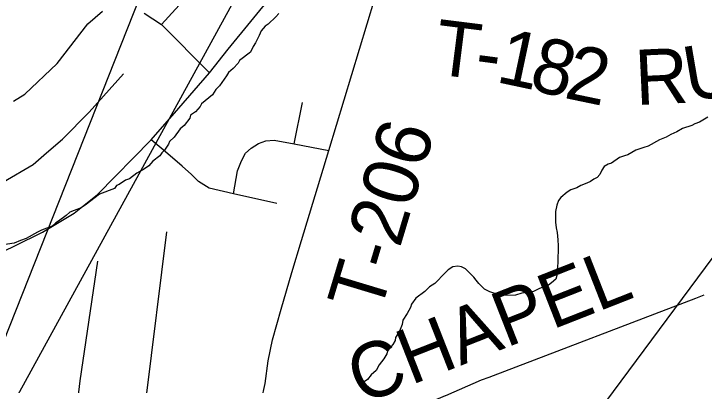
# Model space of a CAD drawing. Extents: x 0 to 39.3, y -3.9 to 22.
# Drawn here: x 4.426 to 5.137, y 18.792 to 19.174 of the extents above; entities that cross this region are included whole.
import ezdxf

# ---------------------------------------------------------------- set-up
doc = ezdxf.new("R2010")
doc.units = 0
for name, color, linetype in [('GM_X_County_Road', 7, 'Continuous'), ('GM_X_County_Road_Text', 7, 'Continuous'), ('GM_X_Minor_River', 7, 'Continuous'), ('GM_X_Township_Road', 7, 'Continuous'), ('GM_X_Township_Road_Text', 7, 'Continuous'), ('SH_Text', 7, 'Continuous')]:
    doc.layers.add(name, color=color, linetype=linetype)

msp = doc.modelspace()

# ---------------------------------------------------------------- linework, layer by layer
at = {"layer": 'GM_X_County_Road'}
msp.add_lwpolyline([(4.59461, 18.67238), (4.59645, 18.67311), (4.60116, 18.67478), (4.62281, 18.68243), (4.66904, 18.70101), (4.73306, 18.72672), (4.73764, 18.72856), (4.73983, 18.72947), (4.85676, 18.77589), (4.87046, 18.7815), (4.87082, 18.78165), (4.90761, 18.79768), (4.9155, 18.80062), (4.91988, 18.80226), (5.12824, 18.88192), (5.13704, 18.8851)], dxfattribs=at)
at = {"layer": 'GM_X_Minor_River'}
for points in [[(4.69882, 19.17461), (4.69572, 19.17124), (4.68762, 19.16378), (4.68454, 19.16155), (4.68066, 19.15706), (4.6783, 19.15215), (4.67475, 19.14461), (4.6724, 19.14085), (4.66964, 19.13481), (4.65809, 19.12627), (4.65691, 19.12362), (4.65149, 19.11801), (4.64686, 19.11391), (4.6449, 19.11052), (4.63751, 19.10038), (4.63364, 19.09665), (4.6305, 19.091), (4.61894, 19.08169), (4.61776, 19.07905), (4.61272, 19.07343), (4.60772, 19.0701), (4.60691, 19.06707), (4.60108, 19.05957), (4.59722, 19.05621), (4.591, 19.04757), (4.58598, 19.0431), (4.58517, 19.04045), (4.58088, 19.03406), (4.57818, 19.03144), (4.57623, 19.02843), (4.56891, 19.02286), (4.56465, 19.01799), (4.55926, 19.01428), (4.55235, 19.0106), (4.54503, 19.00464), (4.54083, 19.00319), (4.53429, 18.99874), (4.53161, 18.99765), (4.52928, 18.99465), (4.51397, 18.98883), (4.50049, 18.97842), (4.4951, 18.97471), (4.48325, 18.97035), (4.47977, 18.96699), (4.47168, 18.96105), (4.46899, 18.95919), (4.46513, 18.95584), (4.45404, 18.95185), (4.4502, 18.94963), (4.43831, 18.94337), (4.43257, 18.94119), (4.42606, 18.93826), (4.41005, 18.93588)], [(5.14069, 19.06795), (5.13224, 19.06278), (5.12727, 19.06134), (5.1242, 19.0595), (5.11464, 19.05624), (5.10888, 19.05292), (5.10238, 19.05037), (5.09776, 19.04741), (5.09088, 19.04487), (5.07936, 19.03823), (5.07478, 19.03679), (5.06637, 19.03427), (5.0583, 19.02947), (5.05487, 19.02839), (5.04951, 19.02658), (5.04143, 19.02064), (5.03799, 19.01956), (5.03377, 19.01735), (5.03143, 19.01359), (5.02945, 19.00906), (5.02674, 19.00606), (5.02328, 19.00422), (5.01983, 19.002), (5.01599, 19.00017), (5.00987, 18.99761), (5.00565, 18.9954), (4.99953, 18.99323), (4.99569, 18.99101), (4.98913, 18.98542), (4.9868, 18.98242), (4.9852, 18.9775), (4.98357, 18.97107), (4.98383, 18.96384), (4.98376, 18.96004), (4.98443, 18.95432), (4.98548, 18.94936), (4.98612, 18.94174), (4.9864, 18.93565), (4.98611, 18.91854), (4.98566, 18.91436), (4.98518, 18.90866), (4.98512, 18.90524), (4.98392, 18.90146), (4.97967, 18.89773), (4.97659, 18.89512), (4.96741, 18.89186), (4.96089, 18.88855), (4.95632, 18.88787), (4.94908, 18.88686), (4.94258, 18.88507), (4.92965, 18.88454), (4.92019, 18.88698), (4.91602, 18.8882), (4.91075, 18.89096), (4.90476, 18.89676), (4.90216, 18.90023), (4.89955, 18.90332), (4.89507, 18.90797), (4.89095, 18.91184), (4.88681, 18.9142), (4.88301, 18.91464), (4.87806, 18.91397), (4.87307, 18.91101), (4.86998, 18.90803), (4.85952, 18.8968), (4.85376, 18.89348), (4.84912, 18.88861), (4.83988, 18.88193), (4.83521, 18.87555), (4.8344, 18.87214), (4.83087, 18.86611), (4.82658, 18.85934), (4.82574, 18.85479), (4.82297, 18.848), (4.81905, 18.84122), (4.81862, 18.83818), (4.81627, 18.83404), (4.81084, 18.82805), (4.81003, 18.82464), (4.8069, 18.81937), (4.80223, 18.81337), (4.79909, 18.80734)], [(4.79909, 18.80734), (4.79369, 18.80287), (4.79019, 18.79798), (4.78558, 18.79502), (4.78172, 18.79205)]]:
    msp.add_lwpolyline(points, dxfattribs=at)
at = {"layer": 'GM_X_Township_Road'}
for p, q in [((4.57793, 19.16339), (4.63728, 19.22911)), ((4.71445, 19.04078), (4.72293, 19.08309))]:
    msp.add_line(p, q, dxfattribs=at)
for points in [[(4.67078, 18.71138), (4.67568, 18.74792), (4.68074, 18.77682), (4.68454, 18.79392), (4.68786, 18.8172), (4.69214, 18.83905), (4.70116, 18.8704), (4.71209, 18.9084), (4.72213, 18.94124), (4.75019, 19.0339), (4.80551, 19.21654)], [(4.26682, 18.90946), (4.29132, 18.90511), (4.33638, 18.90828), (4.37867, 18.91776), (4.40792, 18.92685), (4.4261, 18.93516), (4.45535, 18.94978), (4.48776, 18.96915), (4.51187, 18.98851), (4.56728, 19.04469), (4.59566, 19.07744), (4.62726, 19.11382), (4.64665, 19.13792), (4.69316, 19.19524)], [(4.42551, 19.08436), (4.43697, 19.09187), (4.47022, 19.12314), (4.50178, 19.16396), (4.51712, 19.17729)], [(4.55998, 19.17497), (4.57793, 19.16339), (4.62726, 19.11382)], [(4.25229, 18.98841), (4.26326, 18.98061), (4.2767, 18.97389), (4.29389, 18.97053), (4.31286, 18.96993), (4.32334, 18.97092), (4.34527, 18.97507), (4.36351, 18.97945), (4.36633, 18.98051), (4.36693, 18.98079), (4.38457, 18.98891), (4.41503, 19.00156), (4.44547, 19.01934), (4.4593, 19.0312), (4.4759, 19.04542), (4.50317, 19.07309), (4.53875, 19.11262)], [(4.69649, 18.97931), (4.65184, 18.98919), (4.62708, 18.99491), (4.61606, 19.00193), (4.60861, 19.00894), (4.59903, 19.01752), (4.5797, 19.03441), (4.56728, 19.04469)], [(4.65184, 18.98919), (4.65613, 19.0128), (4.66014, 19.02325), (4.66443, 19.03098), (4.67016, 19.03628), (4.67774, 19.04114), (4.68533, 19.04365), (4.69377, 19.04436), (4.71445, 19.04078), (4.75019, 19.0339)], [(4.41719, 18.76255), (4.47444, 18.7594), (4.49303, 18.75654), (4.53312, 18.75511), (4.54629, 18.75511), (4.55687, 18.7594), (4.56088, 18.7677), (4.56232, 18.78116), (4.58321, 18.95004)], [(4.53125, 18.64487), (4.52152, 18.67519), (4.50472, 18.7237), (4.49303, 18.75654), (4.49104, 18.77028), (4.49411, 18.79671), (4.51222, 18.91999)]]:
    msp.add_lwpolyline(points, dxfattribs=at)
at = {"layer": 'SH_Text'}
for p, q in [((4.29766, 18.54142), (4.86188, 19.96301)), ((4.29766, 18.54142), (4.86188, 19.56973)), ((4.62313, 18.21994), (5.30617, 19.13968))]:
    msp.add_line(p, q, dxfattribs=at)

# ---------------------------------------------------------------- texts
at = {"layer": 'GM_X_County_Road_Text'}
msp.add_text('CHAPEL', height=0.056818, rotation=21.44248, dxfattribs=at).set_placement((4.78367, 18.77204))
at = {"layer": 'GM_X_Township_Road_Text'}
for s, height, rotation, p in [('T', 0.05682, 352.85, (4.85706, 19.11265)), ('1', 0.05682, 347.98993, (4.92111, 19.10452)), ('8', 0.05682, 345.73532, (4.95477, 19.09737)), ('U', 0.05682, 9.76437, (5.12092, 19.08342)), ('2', 0.05682, 348.23924, (4.99133, 19.08814)), ('R', 0.05682, 2.63535, (5.06676, 19.08046)), ('-', 0.05682, 352.4848, (4.89914, 19.10737)), ('T-206', 0.056818, 73.22213, (4.80252, 18.86386))]:
    msp.add_text(s, height=height, rotation=rotation, dxfattribs=at).set_placement(p)

doc.saveas('drawing.dxf')
